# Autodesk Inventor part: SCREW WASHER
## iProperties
Created: 2006-07
Part Number: SCREW WASHER
Material: Steel
Document SubType Name: Modeling
Designer: rollin42
Mass: 1.78877 g
Surface Area: 4.1574 cm^2
Volume: 0.227869 cm^3
Density: 7.85 g/cm^3
Author: rollin42
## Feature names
1. Extrusion1
2. Hole1
3. Extrusion2
